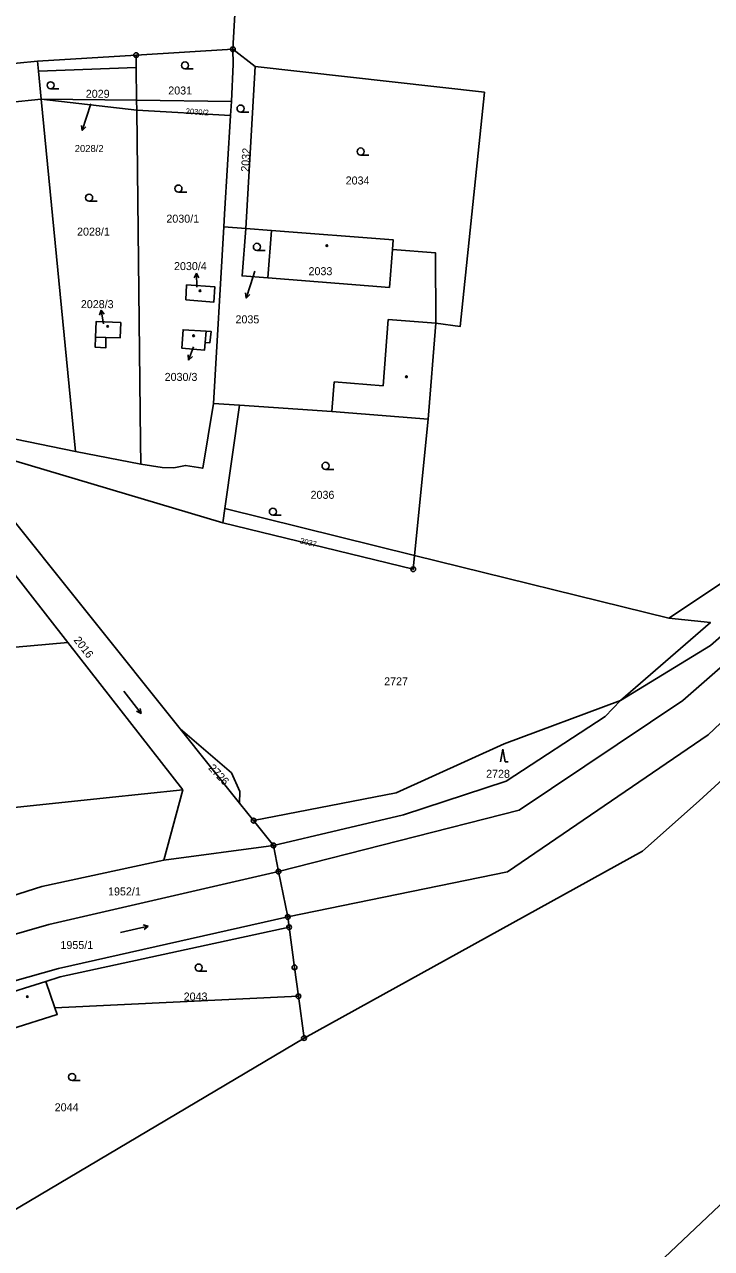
# Model space of a CAD drawing. Extents: x -504988 to -494607, y -1123820 to -1114018.
# Drawn here: x -496126.7 to -495980.9, y -1120695.1 to -1120435.2 of the extents above; entities that cross this region are included whole.
import ezdxf

# ---------------------------------------------------------------- set-up
doc = ezdxf.new("R2010")
doc.units = 0
for name, color, linetype in [('Hranice parcel', 7, 'Continuous'), ('Parcelní čísla', 7, 'Continuous'), ('Pop  PČ popisy', 7, 'Continuous'), ('Vnitřní kresba', 7, 'Continuous'), ('Věcná břemena k části', 7, 'Continuous'), ('Značky bodu BP', 7, 'Continuous'), ('Značky budov', 7, 'Continuous'), ('Značky kultur', 7, 'Continuous')]:
    doc.layers.add(name, color=color, linetype=linetype)

msp = doc.modelspace()

# ---------------------------------------------------------------- linework, layer by layer
at = {"layer": 'Hranice parcel'}
for p, q in [((-496082.49, -1120440.4), (-496072.78, -1120273.25)), ((-496082.49, -1120440.4), (-496103.03, -1120441.66)), ((-496082.49, -1120440.4), (-496077.76, -1120444.09)), ((-496123.94, -1120442.94), (-496173.98, -1120447.87)), ((-496103.03, -1120441.66), (-496123.94, -1120442.94)), ((-496077.76, -1120444.09), (-496079.76, -1120478.47)), ((-496102.9, -1120453.32), (-496123.15, -1120451.01)), ((-496102.92, -1120451.25), (-496123.15, -1120451.01)), ((-496115.86, -1120525.83), (-496123.15, -1120451.01)), ((-496102.9, -1120453.32), (-496102.92, -1120451.25)), ((-496082.81, -1120451.49), (-496102.92, -1120451.25)), ((-496082.99, -1120454.48), (-496102.9, -1120453.32)), ((-496082.99, -1120454.48), (-496082.81, -1120451.49)), ((-496086.6, -1120515.65), (-496084.39, -1120478.11)), ((-496079.76, -1120478.47), (-496084.39, -1120478.11)), ((-496079.76, -1120478.47), (-496074.26, -1120478.9)), ((-496041, -1120518.96), (-496039.39, -1120498.61)), ((-496086.6, -1120515.65), (-496081.09, -1120516.02)), ((-496081.09, -1120516.02), (-496084.2, -1120537.95)), ((-496041, -1120518.96), (-496043.91, -1120547.9)), ((-496084.63, -1120540.97), (-496142.44, -1120523.77)), ((-496142.44, -1120523.77), (-496093.7, -1120584.69)), ((-496115.86, -1120525.83), (-496102.05, -1120528.5)), ((-496084.2, -1120537.95), (-496084.63, -1120540.97)), ((-496084.2, -1120537.95), (-496043.91, -1120547.9)), ((-495981.08, -1120567.02), (-495948.86, -1120538.84)), ((-495989.9, -1120561.22), (-496043.91, -1120547.9)), ((-495978.32, -1120553.48), (-495989.9, -1120561.22)), ((-496253.84, -1120578.57), (-496117.55, -1120566.37)), ((-496117.55, -1120566.37), (-496093.1, -1120597.71)), ((-496000.17, -1120578.71), (-495981.08, -1120567.02)), ((-496000.17, -1120578.71), (-496003.47, -1120582.1)), ((-496003.47, -1120582.1), (-496024.46, -1120595.83)), ((-496081.07, -1120600.48), (-496093.7, -1120584.69)), ((-496097.11, -1120612.62), (-496093.1, -1120597.71)), ((-496081.07, -1120600.48), (-496078.08, -1120604.22)), ((-496073.87, -1120609.48), (-496078.08, -1120604.22)), ((-496097.11, -1120612.62), (-496073.87, -1120609.48)), ((-496073.87, -1120609.48), (-496072.77, -1120615.02)), ((-496070.84, -1120624.68), (-496072.77, -1120615.02)), ((-496070.84, -1120624.68), (-496070.55, -1120626.86)), ((-496146.07, -1120645.84), (-496122.16, -1120638.4)), ((-496120.26, -1120644), (-496122.16, -1120638.4)), ((-496120.26, -1120644), (-496068.57, -1120641.51)), ((-496068.57, -1120641.51), (-496067.38, -1120650.4))]:
    msp.add_line(p, q, dxfattribs=at)
for points in [[(-496082.81, -1120451.49), (-496082.39, -1120443.56), (-496082.49, -1120440.4)], [(-496123.15, -1120451.01), (-496123.78, -1120445.06), (-496123.94, -1120442.94)], [(-496102.92, -1120451.25), (-496103, -1120444.31), (-496103.03, -1120441.66)], [(-496039.39, -1120498.61), (-496034.25, -1120499.3), (-496029.09, -1120449.54), (-496077.76, -1120444.09)], [(-496123.15, -1120451.01), (-496130.07, -1120451.74), (-496128.76, -1120461.47)], [(-496102.05, -1120528.5), (-496102.1, -1120523.75), (-496102.9, -1120453.32)], [(-496084.39, -1120478.11), (-496084.23, -1120475.43), (-496082.99, -1120454.48)], [(-496074.26, -1120478.9), (-496075.04, -1120488.97), (-496080.53, -1120488.54), (-496079.76, -1120478.47)], [(-496048.61, -1120482.91), (-496048.45, -1120480.9), (-496074.26, -1120478.9)], [(-496039.39, -1120498.61), (-496039.5, -1120483.61), (-496048.61, -1120482.91)], [(-496072.77, -1120615.02), (-496021.73, -1120601.98), (-495986.94, -1120578.71), (-495945.74, -1120542.65), (-495915.46, -1120517.15), (-495884.13, -1120494.01), (-495869.11, -1120487.5)], [(-496092.5, -1120493.64), (-496092.32, -1120490.47), (-496086.34, -1120490.86), (-496086.54, -1120494.15), (-496092.5, -1120493.64)], [(-495873.02, -1120496.52), (-495876.55, -1120498.69), (-495923.47, -1120534.47), (-495941.1, -1120547.67), (-495981.59, -1120585.99), (-496024.15, -1120615.12), (-496070.84, -1120624.68)], [(-496106.3, -1120498.41), (-496106.44, -1120501.7), (-496109.42, -1120501.64), (-496109.43, -1120503.8), (-496111.69, -1120503.68), (-496111.64, -1120501.57), (-496111.53, -1120498.24), (-496106.3, -1120498.41)], [(-496088.17, -1120500.27), (-496087.09, -1120500.35), (-496087.34, -1120502.74), (-496088.39, -1120502.66), (-496088.52, -1120504.33), (-496093.34, -1120503.87), (-496093.07, -1120499.99), (-496088.17, -1120500.27)], [(-496102.05, -1120528.5), (-496097.51, -1120529.25), (-496095.02, -1120529.29), (-496092.55, -1120528.77), (-496088.88, -1120529.4), (-496086.6, -1120515.65)], [(-496081.09, -1120516.02), (-496061.49, -1120517.34), (-496041, -1120518.96)], [(-496164.45, -1120521.36), (-496155.89, -1120520.6), (-496148.15, -1120520.06), (-496136.27, -1120521.64), (-496115.86, -1120525.83)], [(-496249.85, -1120537.24), (-496147.8, -1120527.59), (-496117.55, -1120566.37)], [(-496043.91, -1120547.9), (-496044.2, -1120550.84), (-496084.63, -1120540.97)], [(-496067.38, -1120650.4), (-495995.54, -1120610.68), (-495983.47, -1120600), (-495917.46, -1120539.59), (-495897.86, -1120539.98), (-495887.64, -1120553.82), (-495885.39, -1120578.11), (-495887.25, -1120609.9), (-495881.43, -1120635.97), (-495872.96, -1120655.74), (-495858.98, -1120680.97), (-495853.32, -1120679.81)], [(-496000.17, -1120578.71), (-495981.1, -1120562.15), (-495989.9, -1120561.22)], [(-496078.08, -1120604.22), (-496047.8, -1120598.28), (-496024.86, -1120587.9), (-496000.17, -1120578.71)], [(-496093.7, -1120584.69), (-496082.77, -1120594.07), (-496080.99, -1120598.02), (-496081.07, -1120600.48)], [(-496024.46, -1120595.83), (-496046.28, -1120602.99), (-496073.87, -1120609.48)], [(-496093.1, -1120597.71), (-496109.41, -1120599.41), (-496153.12, -1120603.97)], [(-496219.05, -1120646.79), (-496208.37, -1120645.39), (-496123.01, -1120618.2), (-496097.11, -1120612.62)], [(-496198.64, -1120648.69), (-496193.36, -1120646.92), (-496121.52, -1120626.25), (-496072.77, -1120615.02)], [(-496070.84, -1120624.68), (-496119.49, -1120635.64), (-496162.86, -1120647.89)], [(-496122.16, -1120638.4), (-496119.14, -1120637.38), (-496070.55, -1120626.86)], [(-496070.55, -1120626.86), (-496069.4, -1120635.37), (-496068.57, -1120641.51)], [(-496142.27, -1120658.08), (-496129.62, -1120648.52), (-496119.78, -1120645.4), (-496120.26, -1120644)], [(-496150.17, -1120691.24), (-496131.97, -1120688.73), (-496067.38, -1120650.4)]]:
    msp.add_lwpolyline(points, dxfattribs=at)
at = {"layer": 'Pop  PČ popisy'}
for p, q in [((-496112.63, -1120451.98), (-496113.55, -1120454.83)), ((-496113.55, -1120454.83), (-496114.48, -1120457.68)), ((-496114.48, -1120457.68), (-496114.64, -1120456.58)), ((-496114.48, -1120457.68), (-496113.69, -1120456.89)), ((-496090.2, -1120487.94), (-496090.69, -1120488.95)), ((-496090.15, -1120490.94), (-496090.2, -1120487.94)), ((-496090.2, -1120487.94), (-496089.68, -1120488.93)), ((-496077.81, -1120487.56), (-496078.73, -1120490.41)), ((-496079.66, -1120493.26), (-496079.82, -1120492.16)), ((-496078.73, -1120490.41), (-496079.66, -1120493.26)), ((-496079.66, -1120493.26), (-496078.87, -1120492.47)), ((-496110.48, -1120495.79), (-496110.8, -1120496.87)), ((-496109.96, -1120498.75), (-496110.48, -1120495.79)), ((-496110.48, -1120495.79), (-496109.81, -1120496.69)), ((-496091.89, -1120506.41), (-496092.01, -1120505.3)), ((-496090.86, -1120503.59), (-496091.89, -1120506.41)), ((-496091.89, -1120506.41), (-496091.07, -1120505.64))]:
    msp.add_line(p, q, dxfattribs=at)
at = {"layer": 'Vnitřní kresba'}
for p, q in [((-496103, -1120444.31), (-496123.78, -1120445.06)), ((-496048.61, -1120482.91), (-496049.23, -1120490.97)), ((-496049.23, -1120490.97), (-496075.04, -1120488.97)), ((-496050.61, -1120511.86), (-496049.5, -1120497.82)), ((-496049.5, -1120497.82), (-496039.39, -1120498.61)), ((-496088.17, -1120500.27), (-496088.39, -1120502.66)), ((-496111.64, -1120501.57), (-496109.42, -1120501.64)), ((-496061.49, -1120517.34), (-496060.99, -1120511.04)), ((-496060.99, -1120511.04), (-496050.61, -1120511.86))]:
    msp.add_line(p, q, dxfattribs=at)
at = {"layer": 'Věcná břemena k části'}
msp.add_lwpolyline([(-496087.45, -1120791.41), (-496078.91, -1120795.46), (-496073.32, -1120788.44), (-496070.74, -1120785.42), (-496067.96, -1120782.59), (-495886.92, -1120611.38), (-495887.25, -1120609.9), (-495886.58, -1120598.4), (-496074.28, -1120775.91), (-496077.52, -1120779.2), (-496080.52, -1120782.71)], close=True, dxfattribs=at)
at = {"layer": 'Značky bodu BP'}
for centre, radius in [((-496082.49, -1120440.4), 0.5), ((-496082.49, -1120440.4), 0.0303), ((-496103.03, -1120441.66), 0.5), ((-496103.03, -1120441.66), 0.0303), ((-496044.2, -1120550.84), 0.5), ((-496044.2, -1120550.84), 0.0303), ((-496078.08, -1120604.22), 0.5), ((-496078.08, -1120604.22), 0.0303), ((-496073.87, -1120609.48), 0.5), ((-496073.87, -1120609.48), 0.0303), ((-496072.77, -1120615.02), 0.5), ((-496072.77, -1120615.02), 0.0303), ((-496070.84, -1120624.68), 0.5), ((-496070.84, -1120624.68), 0.0303), ((-496070.55, -1120626.86), 0.5), ((-496070.55, -1120626.86), 0.0303), ((-496069.4, -1120635.37), 0.5), ((-496069.4, -1120635.37), 0.0303), ((-496068.57, -1120641.51), 0.5), ((-496068.57, -1120641.51), 0.0303), ((-496067.38, -1120650.4), 0.5), ((-496067.38, -1120650.4), 0.0303)]:
    msp.add_circle(centre, radius, dxfattribs=at)
at = {"layer": 'Značky budov'}
for centre in [(-496062.52, -1120482.11), (-496089.47, -1120491.7), (-496109.08, -1120499.25), (-496090.84, -1120501.26), (-496045.64, -1120509.97), (-496126.11, -1120641.59)]:
    msp.add_circle(centre, 0.175, dxfattribs=at)
at = {"layer": 'Značky kultur'}
for p, q in [((-496092.64, -1120444.59), (-496090.89, -1120444.59)), ((-496121.18, -1120448.81), (-496119.43, -1120448.81)), ((-496080.85, -1120453.75), (-496079.1, -1120453.75)), ((-496055.36, -1120462.88), (-496053.61, -1120462.88)), ((-496094.04, -1120470.74), (-496092.29, -1120470.74)), ((-496113.01, -1120472.68), (-496111.26, -1120472.68)), ((-496077.38, -1120483.12), (-496075.63, -1120483.12)), ((-496062.81, -1120529.63), (-496061.06, -1120529.63)), ((-496073.99, -1120539.37), (-496072.24, -1120539.37)), ((-496105.64, -1120576.74), (-496101.95, -1120581.46)), ((-496101.95, -1120581.46), (-496102.95, -1120581)), ((-496101.95, -1120581.46), (-496102.16, -1120580.38)), ((-496025.2, -1120589.05), (-496025.7, -1120591.73)), ((-496024.7, -1120591.73), (-496025.2, -1120589.05)), ((-496024.7, -1120591.73), (-496024.03, -1120591.73)), ((-496106.33, -1120627.95), (-496100.49, -1120626.6)), ((-496100.49, -1120626.6), (-496101.55, -1120626.33)), ((-496100.49, -1120626.6), (-496101.33, -1120627.31)), ((-496089.75, -1120636.17), (-496088, -1120636.17)), ((-496116.62, -1120659.4), (-496114.87, -1120659.4))]:
    msp.add_line(p, q, dxfattribs=at)
for centre in [(-496092.64, -1120443.84), (-496121.18, -1120448.06), (-496080.85, -1120453), (-496055.36, -1120462.13), (-496094.04, -1120469.99), (-496113.01, -1120471.93), (-496077.38, -1120482.37), (-496062.81, -1120528.88), (-496073.99, -1120538.62), (-496089.75, -1120635.42), (-496116.62, -1120658.65)]:
    msp.add_circle(centre, 0.75, dxfattribs=at)

# ---------------------------------------------------------------- texts
at = {"layer": 'Parcelní čísla'}
for s, height, p in [('2031', 1.7, (-496096.2, -1120450.02)), ('2029', 1.7, (-496113.71, -1120450.72)), ('2028/2', 1.5, (-496116.06, -1120462.24)), ('2034', 1.7, (-496058.54, -1120469.13)), ('2030/1', 1.7, (-496096.6, -1120477.24)), ('2028/1', 1.7, (-496115.56, -1120479.99)), ('2030/4', 1.7, (-496094.98, -1120487.31)), ('2033', 1.7, (-496066.42, -1120488.39)), ('2028/3', 1.7, (-496114.76, -1120495.39)), ('2035', 1.7, (-496081.93, -1120498.62)), ('2030/3', 1.7, (-496096.97, -1120510.84)), ('2036', 1.7, (-496065.99, -1120535.88)), ('2727', 1.7, (-496050.37, -1120575.49)), ('2728', 1.7, (-496028.72, -1120595.12)), ('1952/1', 1.7, (-496108.98, -1120620.1)), ('1955/1', 1.7, (-496119.09, -1120631.48)), ('2043', 1.7, (-496092.93, -1120642.42)), ('2044', 1.7, (-496120.31, -1120665.94))]:
    msp.add_text(s, height=height, dxfattribs=at).set_placement(p)
for s, height, rotation, p in [('2030/2', 1.2, 356, (-496092.54, -1120454.14)), ('2032', 1.7, 86, (-496079.09, -1120466.48)), ('2037', 1.2, 346, (-496068.33, -1120545.29)), ('2016', 1.7, 308, (-496116.38, -1120565.91)), ('2726', 1.7, 313, (-496087.81, -1120593.16))]:
    msp.add_text(s, height=height, rotation=rotation, dxfattribs=at).set_placement(p)

doc.saveas('drawing.dxf')
